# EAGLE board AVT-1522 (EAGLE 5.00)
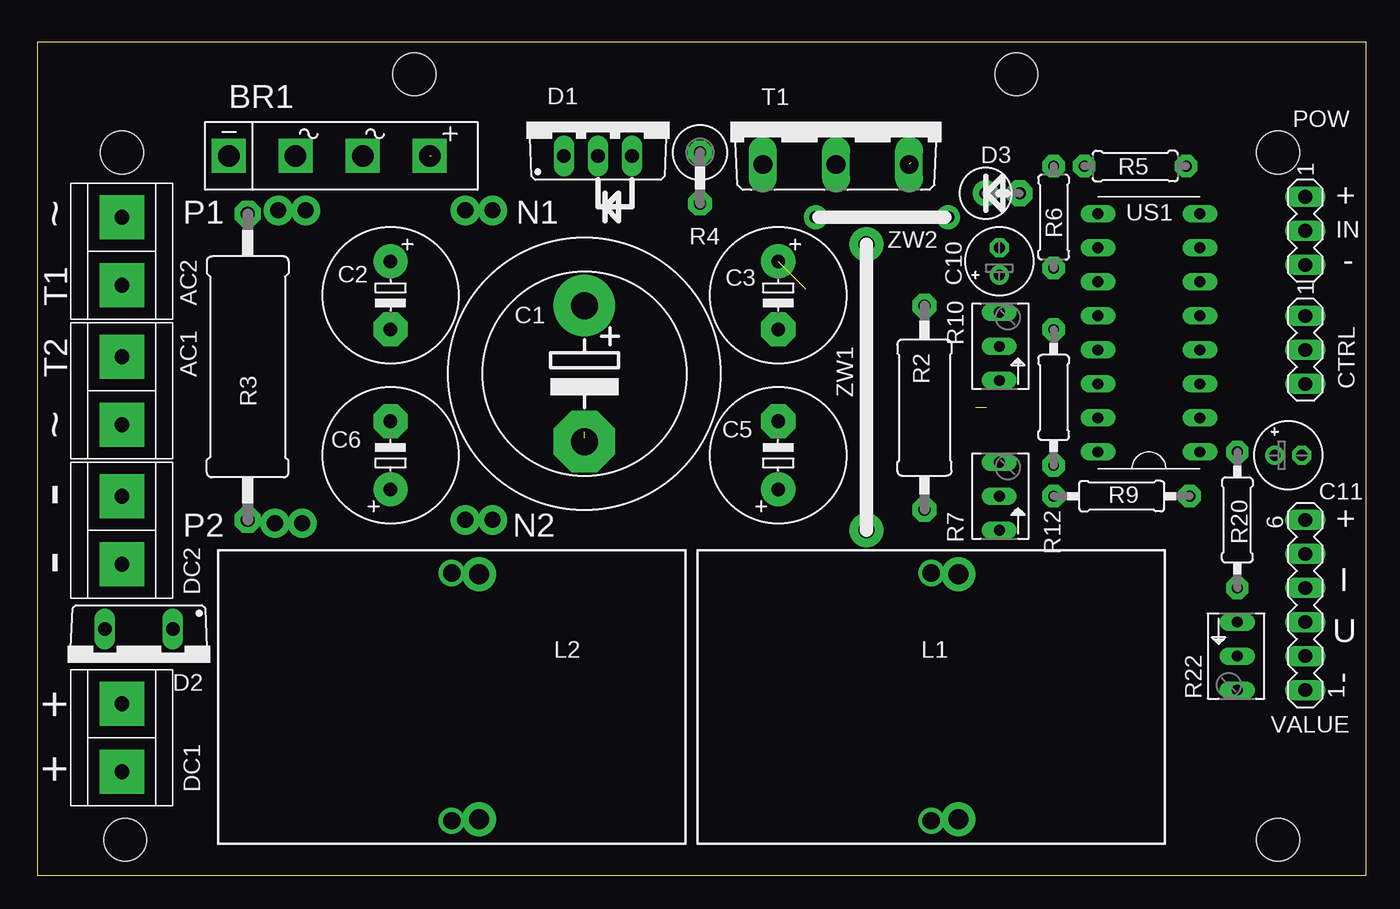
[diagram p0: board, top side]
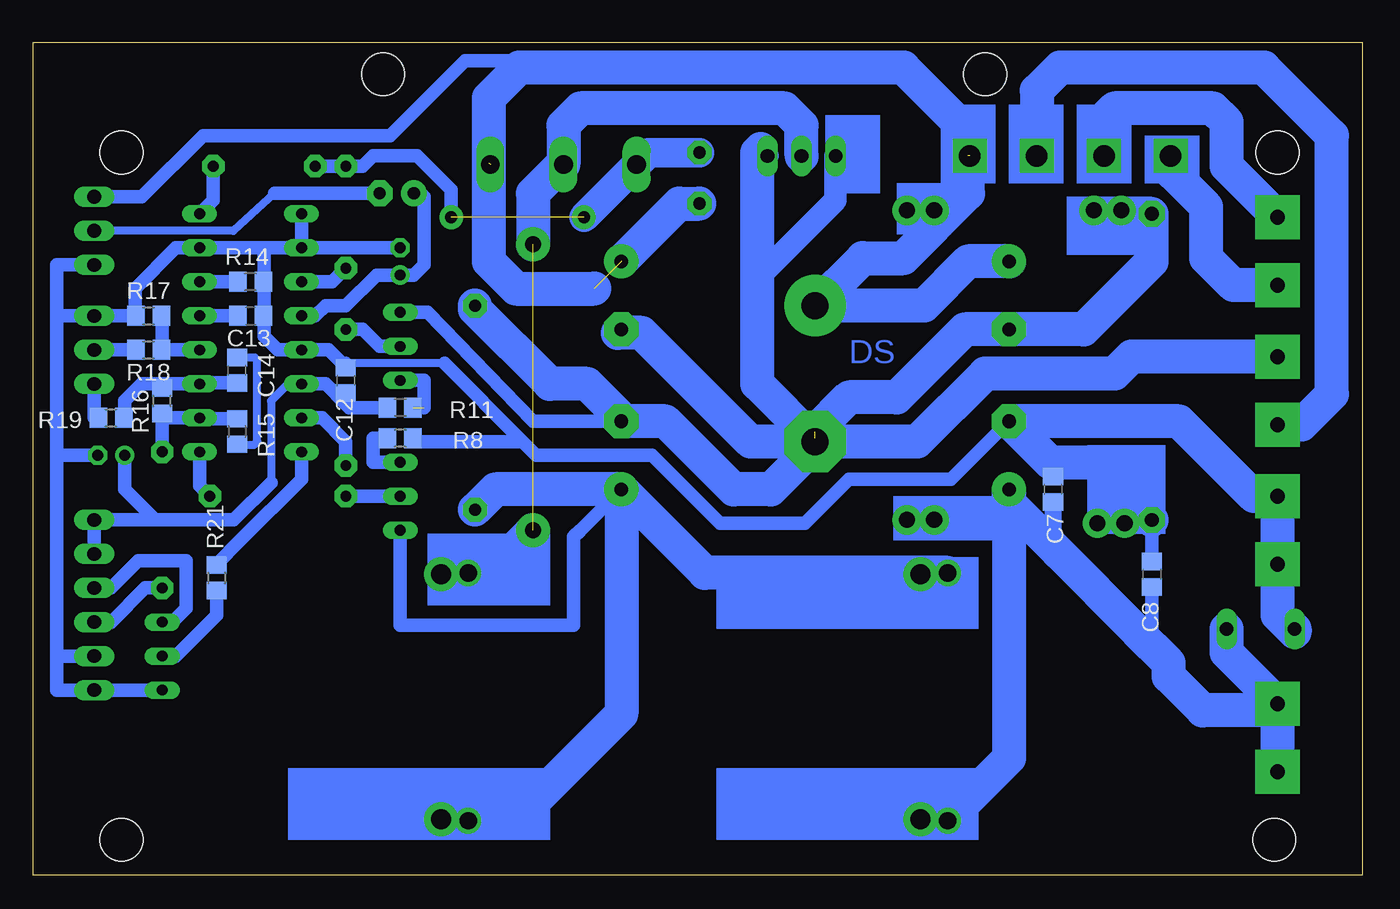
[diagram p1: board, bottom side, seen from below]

Size 99.24 x 62.22 mm. Coordinates in mm from the lower left corner, seen from the top.
Outline: 0,0 99.24,0 99.24,62.22 0,62.22 0,0
Copper layers (1*16): Top 0.035mm / dielectric 1.5mm / Bottom 0.035mm
Design rules "default": minimum track width 10mil, minimum drill 24mil, track to track 8mil, track to pad 8mil, pad to pad 8mil, via to via 8mil, smd to smd 8mil, copper to edge 40mil, drill to drill 8mil, minimum pad ring 10mil, minimum via ring 8mil, stop-mask expansion 4mil, vias tented up to drill 0mil, thermal gap 10mil
Holes 3.2 mm at 6.31,53.97 6.57,2.66 92.67,53.97 92.67,2.66 28.16,59.81 73.11,59.81

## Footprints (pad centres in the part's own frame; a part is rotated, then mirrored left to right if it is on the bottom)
ARK500/2 = drill 1.1 pad 3.302 square: 1 -2.54,0; 2 2.54,0
FB15A = drill 1.6 pad 2.54 square: + -7.5,0; - 7.511,0; AC1 -2.496,0; AC2 2.533,0
EB20D = drill 2.007 pad 4.597 round: + -5.08,0 | drill 2.007 pad 4.597 octagon: - 5.08,0
E5-10,5 = drill 1.016 pad 2.54 round: + -2.54,0 | drill 1.016 pad 2.54 octagon: - 2.54,0
C0805 = smd 1.3 x 1.5: 1 -0.95,0; 2 0.95,0
E2-5 = drill 0.813 pad 1.422 round: + -1.016,0 | drill 0.813 pad 1.422 octagon: - 1.016,0
MA03-1 = drill 1.016 long: 1 -2.54,0; 2 0,0; 3 2.54,0
TO220ABS = drill 1.016 long: A1 -2.54,-2.54; A2 2.54,-2.54; C 0,-2.54
DO220S = drill 1.016 long: A 2.54,-2.54; C -2.54,-2.54
RAD2,5 = drill 0.9 pad 1.93 octagon: A 1.27,0 | drill 0.9 pad 1.93 round: C -1.27,0
TJ6-U1 = drill 1.3 round: 1 -9.25,0; 2 9.25,0
0411/15 = drill 0.914 pad 1.778 octagon: 1 -7.62,0; 2 7.62,0
0617/22 = drill 1.016 pad 1.93 octagon: 1 -11.43,0; 2 11.43,0
0411V = drill 0.914 pad 1.778 octagon: 1 -2.54,0; 2 1.27,0
0207/7 = drill 0.813 pad 1.676 octagon: 1 -3.81,0; 2 3.81,0
B64Y = drill 0.813 long: A 2.54,0; E -2.54,0; S 0,0
R0805 = smd 1.3 x 1.5: 1 -0.95,0; 2 0.95,0
0207/10 = drill 0.813 pad 1.676 octagon: 1 -5.08,0; 2 5.08,0
TOP3AV = drill 1.397 long: B -5.461,-3.175; C 0,-3.175; E 5.461,-3.175
DIL16 = drill 0.8 long: 1 -8.89,-3.81; 2 -6.35,-3.81; 3 -3.81,-3.81; 4 -1.27,-3.81; 5 1.27,-3.81; 6 3.81,-3.81; 7 6.35,-3.81; 8 8.89,-3.81; 9 8.89,3.81; 10 6.35,3.81; 11 3.81,3.81; 12 1.27,3.81; 13 -1.27,3.81; 14 -3.81,3.81; 15 -6.35,3.81; 16 -8.89,3.81
MA06-1 = drill 1.016 long: 1 -6.35,0; 2 -3.81,0; 3 -1.27,0; 4 1.27,0; 5 3.81,0; 6 6.35,0

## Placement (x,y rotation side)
AC1  ARK500/2  [ARK500/2]  6.31,36.19 90 top
AC2  ARK500/2  [ARK500/2]  6.31,46.6 90 top
BR1  8A  [FB15A]  21.81,53.72 180 top
C1  4700uF  [EB20D]  40.86,37.46 270 top
C2  220uF  [E5-10,5]  26.38,43.3 270 top
C3  220uF  [E5-10,5]  55.33,43.3 270 top
C5  220uF  [E5-10,5]  55.33,31.36 90 top
C6  220uF  [E5-10,5]  26.38,31.36 90 top
C7  100nF  [C0805]  23.08,28.82 90 bottom
C8  100nF  [C0805]  15.71,22.47 90 bottom
C10  10uF  [E2-5]  71.84,45.84 90 top
C11  220uF  [E2-5]  93.43,31.36 0 top
C12  100n  [C0805]  75.91,36.95 90 bottom
C13  1,5nF  [C0805]  83.02,41.78 180 bottom
C14  100n  [C0805]  84.04,37.71 270 bottom
CTRL  [MA03-1]  94.7,39.24 270 top
D1  F16C20  [TO220ABS]  41.87,56.26 0 top
D2  BYW29  [DO220S]  7.58,15.87 180 top
D3  1N4007  [RAD2,5]  72.1,50.92 0 top
DC1  ARK500/2  [ARK500/2]  6.31,10.28 90 top
DC2  ARK500/2  [ARK500/2]  6.31,25.78 90 top
L1  50uH 10A  [TJ6-U1]  66.76,13.33 270 top
L2  100uH 5A  [TJ6-U1]  30.95,13.33 270 top
POW  [MA03-1]  94.7,48.13 270 top
R2  2,2k  [0411/15]  66.26,34.92 270 top
R3  0,1R  [0617/22]  15.71,37.97 90 top
R4  1k  [0411V]  49.49,51.43 270 top
R5  330R  [0207/7]  82,52.95 180 top
R6  330R  [0207/7]  75.91,49.14 90 top
R7  10k  [B64Y]  71.84,28.32 90 top
R8  1k  [R0805]  71.84,32.63 180 bottom
R9  1k  [0207/10]  80.99,28.32 0 top
R10  10k  [B64Y]  71.84,39.49 90 top
R11  10k  [R0805]  71.84,34.92 180 bottom
R12  1k  [0207/10]  75.91,35.68 90 top
R14  10k  [R0805]  83.02,44.32 180 bottom
R15  47k  [R0805]  84.04,33.14 270 bottom
R16  1M  [R0805]  89.62,35.43 90 bottom
R17  10k  [R0805]  90.64,41.78 0 bottom
R18  1k  [R0805]  90.64,39.24 0 bottom
R19  1k  [R0805]  93.43,34.16 0 bottom
R20  1k  [0207/10]  89.62,26.54 270 top
R21  1k  [R0805]  85.56,22.22 270 bottom
R22  10k  [B64Y]  89.62,16.38 270 top
T1  BDW84C  [TOP3AV]  59.65,56.26 0 top
US1  [DIL16]  83.02,40.51 90 top
VALUE  [MA06-1]  94.7,20.19 90 top

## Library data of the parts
AC1 AC2 DC1 DC2 US1 = DS
BR1 = rectifier
C1-C3 C5-C8 C10-C14 L1 L2 R2-R6 R8 R9 R11 R12 R14-R21 = rcl
CTRL POW VALUE = con-lstb
D1-D3 = diode
R7 R10 R22 = pot
T1 = transistor-power

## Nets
+5V: C11.+ C12.1 R11.2 US1.14 VALUE.5 VALUE.6
GND: C6.- C7.2 C8.2 C10.- C11.- C12.2 C13.1 CTRL.1 D2.A DC2.1 DC2.2 POW.3 R3.1 R8.1 R14.1 R17.1 R22.A US1.7 US1.9 US1.10 US1.13 VALUE.1 VALUE.2
N$1: C5.+ L1.2 L2.1 R2.2 R7.E
N$2: AC1.2 C1.- C2.- C3.- C5.- D1.A1 D1.A2 R2.1 R3.2 R10.A
N$3: AC2.2 BR1.AC2
N$4: R4.1 R5.2 R6.2 T1.B
N$5: R21.2 R22.S
N$6: R14.2 US1.6
N$7: R22.E VALUE.4
N$8: C14.1 R15.2
N$10: C13.2 US1.5
N$11: R7.A R8.2
N$12: C6.+ C7.1 C8.1 D2.C DC1.1 DC1.2 L2.2
N$13: AC1.1 BR1.AC1
N$16: D1.C L1.1 T1.C
N$17: R15.1 R16.1 R20.1 US1.2
N$18: R17.2 R18.2 US1.4
N$19: R10.E R11.1
N$20: R10.S R12.2
N$21: R7.S R9.1
N$22: R21.1 US1.16
N$23: R6.1 US1.11
N$24: C10.+ D3.C US1.12
N$25: R5.1 US1.8
N$26: R12.1 US1.15
N$27: R9.2 US1.1
N$28: C14.2 R16.2 R19.2 US1.3
N$29: D3.A POW.2
N$30: CTRL.2 R18.1
N$31: CTRL.3 R19.1
N$33: R20.2 VALUE.3
N$34: AC2.1 BR1.-
VCC: BR1.+ C1.+ C2.+ C3.+ POW.1 R4.2 T1.E

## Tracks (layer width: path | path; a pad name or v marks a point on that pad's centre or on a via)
+5V
  Bottom 0.61: 78.96,36.7 US1.14 80.23,36.7 81.5,35.43 81.5,29.33
  Bottom 1.016: 81.5,29.33 84.29,26.54 90.13,26.54 | 90.13,26.54 VALUE.6 VALUE.5 | C11.+ 92.42,28.82 90.13,26.54 | US1.14 77.43,36.7 75.91,35.17 | 75.91,35.17 75.65,34.92 R11.2 | 75.91,35.17 C12.1
GND
  Bottom 0.61: 68.54,38.22 75.91,38.22
  Bottom 1.016: 82,41.78 C13.1 | 82,41.78 82,44.25 R14.1 82,44.38 82,46.86 | 82,46.86 US1.10 | 82,46.86 US1.7 88.61,46.86 91.66,43.81 91.66,41.78 R17.1 94.96,41.78 | US1.10 US1.9 | 82,41.78 82,40.25 80.99,39.24 US1.13 77.18,39.24 75.91,37.97 C12.2 75.91,38.22 | 97.5,16.38 97.5,13.84 94.96,13.84 | 97.5,41.52 97.5,31.36 | 97.5,31.36 97.5,16.38 | 97.5,41.52 97.5,41.78 94.96,41.78 | 97.5,16.38 VALUE.2 | POW.3 97.5,45.59 97.5,41.52 | 94.96,41.78 CTRL.1 | 97.5,31.36 C11.- | US1.10 C10.- | R8.1 70.89,32.45 70.83,32.38 62.7,32.38 | 62.7,32.38 61.68,31.36 53.05,31.36 47.97,26.28 43.14,26.28 41.62,26.28 38.32,29.59 30.7,29.59 C6.- | 62.7,32.38 68.54,38.22 | 94.96,13.84 VALUE.1 | 94.96,13.84 R22.A | R3.1 C8.2
  Bottom 1.27: 23.08,30.86 C7.2
  Bottom 2.54: DC2.1 6.31,22.98 | DC2.1 DC2.2 8.09,28.32 13.68,33.9 C6.- 23.33,30.86 23.08,30.86 20.03,30.86 R3.1 | D2.A 5.04,18.16 6.31,19.43 DC2.1
N$1
  Bottom 1.016: C5.+ 58.38,25.78 58.89,25.27 58.89,18.66 71.84,18.66 R7.E
  Bottom 2.54: C5.+ 55.33,12.06 63.46,3.93 66.51,3.93 66.66,4.08 L1.2 | C5.+ 55.33,28.57 55.59,28.82 64.73,28.82 R2.2 | L2.1 49.09,22.58 C5.+
N$2  (1 unrouted)
  Bottom 1.016: R10.A 69.81,42.03 61.94,33.9 C5.-
  Bottom 1.676: 45.17,52.95 45.43,52.95 44.67,53.72 D1.A2 | D1.A1 39.33,50.41 45.17,44.57
  Bottom 2.54: 40.6,32.38 33.24,32.38 28.16,37.46 18.5,37.46 17.23,38.73 AC1.2 | C3.- 55.59,40.51 53.81,40.51 45.68,32.38 41.11,32.38 40.86,32.63 C1.- | R3.2 15.71,45.84 20.79,40.76 C2.- | 40.86,33.14 38.32,35.68 34.76,35.68 29.68,40.76 C2.- | C2.- 26.12,40.76 | C1.- 45.17,36.7 45.17,44.57 45.17,52.95 45.17,53.97 44.92,54.22 | 55.08,33.9 52.03,33.9 46.95,28.82 44.16,28.82 40.6,32.38 | 40.6,32.38 C1.- | R2.1 66.26,42.29 60.67,36.7 57.87,36.7 55.08,33.9 | 55.08,33.9 C5.-
N$3
  Bottom 2.54: BR1.AC2 19.27,56.5 18.5,57.27 11.14,57.27 10.12,56.26 10.12,52.95 AC2.2
N$4  (via drill 0.9 pad 1.78)  (1 unrouted)
  Bottom 1.016: R5.2 R6.2 74.64,52.95 73.88,53.72 70.57,53.72 68.03,51.18 v68.03,49.14
  Bottom 2.184: 54.06,53.21 53.3,53.97 R4.1 | 54.06,53.21 T1.B | 54.06,53.21 v58.13,49.14
N$5
  Bottom 1.016: R21.2 85.56,19.43 88.61,16.38 R22.S
N$6
  Bottom 1.016: R14.2 US1.6
N$7
  Bottom 1.016: VALUE.4 93.43,21.46 91.4,23.49 87.85,23.49 87.85,19.93 88.86,18.92 R22.E 89.88,18.92
N$8
  Bottom 0.61: C14.1 82.7,38.66 82.51,38.48 82.51,32.38 82.77,32.13 84.04,32.13 R15.2
N$9  (via drill 1.5 pad 2.54)
  other vias: 32.98,22.47
N$10
  Bottom 1.016: C13.2 US1.5
N$11
  Bottom 1.016: R8.2 73.88,32.63 73.88,30.86 R7.A
N$12
  Bottom 1.016: 15.71,18.03 15.71,17.9 | 16.85,18.28 15.71,18.03 | 15.71,18.03 C8.1
  Bottom 1.27: 22.7,24.12 23.08,25.78 C7.1
  Bottom 2.54: D2.C 10.12,16.63 DC1.2 6.57,12.57 | L2.2 30.95,4.19 26.38,8.76 C6.+ 26.38,27.81 22.7,24.12 16.85,18.28 14.44,15.87 14.44,14.85 11.9,12.31 6.82,12.31 6.57,12.57 | DC1.1 6.31,12.31 6.57,12.57
N$13
  Bottom 2.54: BR1.AC1 24.3,58.59 22.57,60.32 7.33,60.32 2.25,55.24 2.25,35.94 4.53,33.65 AC1.1
N$14  (via drill 1.5 pad 2.54)
  other vias: 32.98,4.19
N$15  (via drill 1.5 pad 2.54)
  other vias: 68.8,4.19
N$16  (via drill 1.2 pad 2.54)  (1 unrouted)
  Bottom 2.54: D1.C 41.87,56 43.14,57.27 58.38,57.27 59.65,56 59.65,53.21 | L1.1 65.13,22.58 v61.94,25.78 | v61.94,47.11 61.94,50.92 59.65,53.21 | 59.65,53.21 T1.C
N$17
  Bottom 1.016: R15.1 86.76,34.09 US1.2 89.37,34.16 89.62,34.41 R16.1 R20.1
N$18
  Bottom 1.016: US1.4 89.62,39.24 | 89.62,39.24 R18.2 | R17.2 89.62,41.46 89.62,39.24
N$19  (1 unrouted)
  Bottom 1.016: R10.E 70.07,36.95 70.07,34.92
N$20
  Bottom 1.016: R12.2 74.64,40.76 73.37,39.49 R10.S
N$21
  Bottom 1.016: R7.S R9.1
N$22
  Bottom 1.016: US1.16 79.21,29.59 83.78,25.01 85.56,23.24 R21.1
N$23
  Bottom 1.016: US1.11 76.92,44.32 R6.1
N$24
  Bottom 1.016: US1.12 78.19,41.78 77.43,42.54 75.91,42.54 73.62,44.83 C10.+ 70.83,44.83 70.07,45.59 70.07,50.67 70.32,50.92 D3.C
N$25
  Bottom 1.016: US1.8 85.81,50.41 R5.1
N$26
  Bottom 1.016: US1.15 77.69,34.16 75.91,32.38 R12.1
N$27
  Bottom 1.016: US1.1 86.83,29.08 R9.2
N$28
  Bottom 1.016: C14.2 86.76,36.76 US1.3 89.62,36.7 | 89.62,36.7 91.15,36.7 92.42,35.43 92.42,34.16 R19.2 | 89.62,36.7 R16.2
N$29
  Bottom 0.61: POW.2 84.29,48.13 81.24,50.92
  Bottom 1.016: POW.2 94.96,48.13 | D3.A 81.24,50.92
N$30
  Bottom 1.016: 91.4,39.24 R18.1 CTRL.2
N$31
  Bottom 1.016: R19.1 94.38,33.97 94.45,33.9 94.7,34.16 CTRL.3
N$32  (via drill 1.5 pad 2.54)
  other vias: 68.8,22.47
N$33
  Bottom 1.016: VALUE.3 93.43,18.92 90.89,21.46 R20.2
N$34
  Bottom 2.54: AC2.1 9.61,44.06 11.65,46.1 11.65,49.91 14.19,52.45 14.19,53.46 14.29,53.57 BR1.-
N$35  (via drill 1.2 pad 2.18)
  other vias: 17.74,26.28
N$36  (via drill 1.2 pad 2.18)
  other vias: 18,49.65
N$37  (via drill 1.2 pad 2.18)
  other vias: 20.03,49.65
N$38  (via drill 1.2 pad 2.18)
  other vias: 19.77,26.28
N$39  (via drill 1.2 pad 2.18)
  other vias: 34,49.65
N$40  (via drill 1.2 pad 2.18)
  other vias: 31.97,49.65
N$41  (via drill 1.2 pad 2.18)
  other vias: 34,26.54
N$42  (via drill 1.2 pad 2.18)
  other vias: 31.97,26.54
VCC  (3 unrouted)
  Bottom 1.016: POW.1 91.15,50.67 86.58,55.24 72.61,55.24 67.02,60.83 63.21,60.83 62.7,60.32
  Bottom 2.54: 65.24,53.21 65.24,58.03 62.95,60.32 62.7,60.32 34.25,60.32 29.43,55.49 29.43,53.72 | 65.24,53.21 65.24,52.19 | 65.24,53.21 65.24,45.84 63.21,43.81 57.37,43.81 | R4.2 51.02,50.16 C3.+ | BR1.+ 29.43,53.6 29.43,50.92 34.25,46.1 37.3,46.1 C1.+ 32.73,42.54 29.43,45.84 C2.+
(copper drawn outside any net)
  shapes: Bottom area x13

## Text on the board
Bottom: DS
tPlace: + | ~ | P1 | N1 | IN | ZW2 | - | T1 | T2 | ZW1 | ~ | - | + | P2 | N2 | - | I | U | - | + | +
